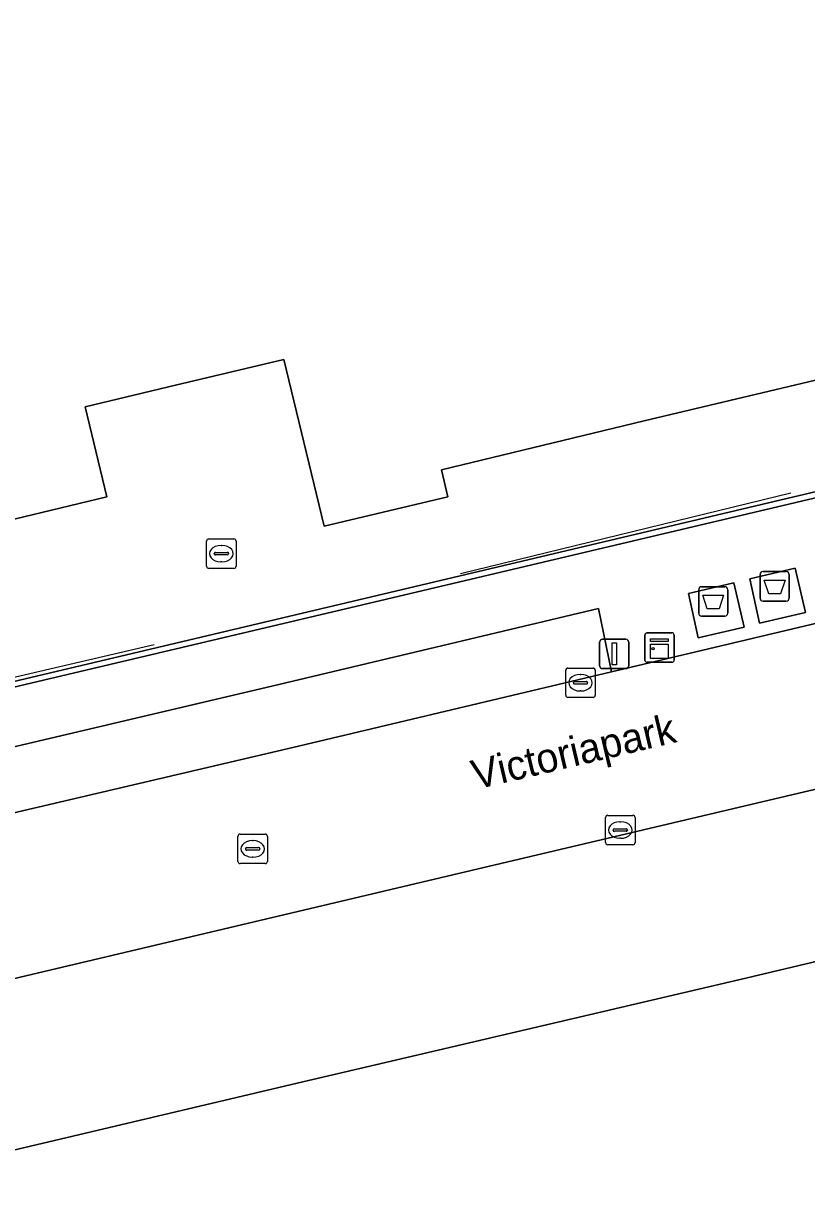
# Model space of a CAD drawing. Extents: x 160675 to 161153, y 383241 to 383714.
# Drawn here: x 160916.35 to 160942.94, y 383443.78 to 383483.75 of the extents above; entities that cross this region are included whole.
import ezdxf

# ---------------------------------------------------------------- set-up
doc = ezdxf.new("R2010")
doc.units = 0
for name, color, linetype in [('IMGEO_Afval_apart_plaats', 7, 'Continuous'), ('IMGEO_Groenvoorziening', 7, 'Continuous'), ('IMGEO_Kast', 7, 'Continuous'), ('IMGEO_Kolk', 7, 'Continuous'), ('IMGEO_Lichtmast', 7, 'Continuous'), ('IMGEO_Lijnafwatering', 7, 'Continuous'), ('IMGEO_Muur', 7, 'Continuous'), ('IMGEO_Openbare_ruimte_label', 7, 'Continuous'), ('IMGEO_Pand', 7, 'Continuous'), ('IMGEO_Parkeervlak_gesloten', 7, 'Continuous'), ('IMGEO_Parkeervlak_open', 7, 'Continuous'), ('IMGEO_Rijbaan_lokaal_gesloten', 7, 'Continuous'), ('IMGEO_Rioolput', 7, 'Continuous'), ('IMGEO_Voetpad_gesloten', 7, 'Continuous'), ('IMGEO_Voetpad_open', 7, 'Continuous')]:
    doc.layers.add(name, color=color, linetype=linetype)

msp = doc.modelspace()

# ---------------------------------------------------------------- linework, layer by layer
at = {"layer": 'IMGEO_Afval_apart_plaats'}
for p, q in [((160941.467, 383465.139), (160942.257, 383465.139)), ((160942.257, 383465.139), (160941.467, 383465.139)), ((160941.367, 383464.239), (160941.367, 383465.039)), ((160941.367, 383465.039), (160941.367, 383464.239)), ((160942.357, 383465.039), (160942.357, 383464.239)), ((160942.357, 383464.239), (160942.357, 383465.039)), ((160939.282, 383463.725), (160939.282, 383464.525)), ((160939.282, 383464.525), (160939.282, 383463.725)), ((160939.382, 383464.625), (160940.172, 383464.625)), ((160940.172, 383464.625), (160939.382, 383464.625)), ((160940.272, 383464.525), (160940.272, 383463.725)), ((160940.272, 383463.725), (160940.272, 383464.525)), ((160942.257, 383464.139), (160941.467, 383464.139)), ((160941.467, 383464.139), (160942.257, 383464.139)), ((160940.172, 383463.625), (160939.382, 383463.625)), ((160939.382, 383463.625), (160940.172, 383463.625))]:
    msp.add_line(p, q, dxfattribs=at)
for points in [[(160941.51, 383464.853), (160942.214, 383464.853), (160942.065, 383464.383), (160941.659, 383464.383), (160941.51, 383464.853)], [(160939.425, 383464.339), (160940.129, 383464.339), (160939.98, 383463.869), (160939.574, 383463.869), (160939.425, 383464.339)]]:
    msp.add_lwpolyline(points, dxfattribs=at)
for centre, start, end in [((160941.467, 383465.039), 90, 180), ((160941.467, 383465.039), 90, 180), ((160942.257, 383465.039), 0, 90), ((160942.257, 383465.039), 360, 90), ((160939.382, 383464.525), 90, 180), ((160939.382, 383464.525), 90, 180), ((160940.172, 383464.525), 0, 90), ((160940.172, 383464.525), 360, 90), ((160941.467, 383464.239), 180, 270), ((160941.467, 383464.239), 180, 270), ((160942.257, 383464.239), 270, 0), ((160942.257, 383464.239), 270, 0), ((160939.382, 383463.725), 180, 270), ((160939.382, 383463.725), 180, 270), ((160940.172, 383463.725), 270, 0), ((160940.172, 383463.725), 270, 0)]:
    msp.add_arc(centre, 0.1, start, end, dxfattribs=at)
at = {"layer": 'IMGEO_Groenvoorziening'}
msp.add_lwpolyline([(160961.401, 383438.272), (160959.945, 383443.924), (160957.181, 383455.143), (160948.323, 383453.092), (160940.889, 383451.334), (160925.647, 383447.762), (160912.456, 383444.655), (160912.313, 383445.09), (160912.097, 383445.102), (160911.285, 383444.92), (160908.049, 383444.567), (160904.275, 383444.678), (160902.028, 383444.954), (160902.501, 383446.376), (160901.449, 383446.503), (160900.213, 383446.777), (160898.49, 383441.561)], dxfattribs=at)
at = {"layer": 'IMGEO_Kast'}
for p, q in [((160937.45, 383462.135), (160937.45, 383462.976)), ((160937.45, 383462.976), (160937.45, 383462.135)), ((160937.525, 383463.06), (160938.366, 383463.06)), ((160938.366, 383463.06), (160937.525, 383463.06)), ((160938.45, 383462.985), (160938.45, 383462.144)), ((160938.45, 383462.144), (160938.45, 383462.985)), ((160938.375, 383462.06), (160937.534, 383462.06)), ((160937.534, 383462.06), (160938.375, 383462.06))]:
    msp.add_line(p, q, dxfattribs=at)
for points in [[(160937.645, 383462.85), (160938.245, 383462.85), (160938.245, 383462.765), (160937.645, 383462.765), (160937.645, 383462.85)], [(160937.645, 383462.675), (160938.245, 383462.675), (160938.245, 383462.186), (160937.645, 383462.186), (160937.645, 383462.675)]]:
    msp.add_lwpolyline(points, dxfattribs=at)
msp.add_circle((160937.729, 383462.524), 0.0377, dxfattribs=at)
for centre, start, end in [((160938.372, 383462.982), 2.4484, 94.2845), ((160938.372, 383462.982), 2.4484, 94.2845), ((160937.528, 383462.982), 92.4484, 184.2845), ((160937.528, 383462.982), 92.4484, 184.2845), ((160937.528, 383462.138), 182.4484, 274.2845), ((160937.528, 383462.138), 182.4484, 274.2845), ((160938.372, 383462.138), 272.4484, 4.2845), ((160938.372, 383462.138), 272.4484, 4.2845)]:
    msp.add_arc(centre, 0.0779, start, end, dxfattribs=at)
at = {"layer": 'IMGEO_Kolk'}
for p, q in [((160922.567, 383465.323), (160922.567, 383466.175)), ((160922.642, 383466.249), (160923.494, 383466.249)), ((160923.055, 383466.029), (160923.08, 383466.029)), ((160923.568, 383466.175), (160923.568, 383465.323)), ((160922.826, 383465.743), (160922.826, 383465.755)), ((160923.264, 383465.706), (160922.866, 383465.706)), ((160922.869, 383465.792), (160923.267, 383465.792)), ((160923.078, 383465.469), (160923.053, 383465.469)), ((160923.31, 383465.755), (160923.31, 383465.743)), ((160923.494, 383465.249), (160922.642, 383465.249)), ((160934.841, 383461.864), (160935.693, 383461.864)), ((160934.766, 383460.938), (160934.766, 383461.79)), ((160935.254, 383461.644), (160935.279, 383461.644)), ((160935.767, 383461.79), (160935.767, 383460.938)), ((160935.025, 383461.358), (160935.025, 383461.37)), ((160935.463, 383461.321), (160935.065, 383461.321)), ((160935.068, 383461.407), (160935.466, 383461.407)), ((160935.277, 383461.084), (160935.252, 383461.084)), ((160935.509, 383461.37), (160935.509, 383461.358)), ((160935.693, 383460.864), (160934.841, 383460.864)), ((160936.119, 383455.934), (160936.119, 383456.786)), ((160936.194, 383456.86), (160937.046, 383456.86)), ((160937.12, 383456.786), (160937.12, 383455.934)), ((160936.378, 383456.354), (160936.378, 383456.366)), ((160936.816, 383456.317), (160936.418, 383456.317)), ((160936.421, 383456.403), (160936.819, 383456.403)), ((160936.607, 383456.64), (160936.632, 383456.64)), ((160936.862, 383456.366), (160936.862, 383456.354)), ((160936.63, 383456.08), (160936.605, 383456.08)), ((160937.046, 383455.86), (160936.194, 383455.86))]:
    msp.add_line(p, q, dxfattribs=at)
for points in [[(160922.567, 383465.323), (160922.567, 383466.175)], [(160922.642, 383466.249), (160923.494, 383466.249)], [(160923.568, 383466.175), (160923.568, 383465.323)], [(160923.494, 383465.249), (160922.642, 383465.249)], [(160934.841, 383461.864), (160935.693, 383461.864)], [(160934.766, 383460.938), (160934.766, 383461.79)], [(160935.767, 383461.79), (160935.767, 383460.938)], [(160935.693, 383460.864), (160934.841, 383460.864)], [(160936.119, 383455.934), (160936.119, 383456.786)], [(160936.194, 383456.86), (160937.046, 383456.86)], [(160937.12, 383456.786), (160937.12, 383455.934)], [(160937.046, 383455.86), (160936.194, 383455.86)]]:
    msp.add_lwpolyline(points, dxfattribs=at)
for centre, radius, start, end in [((160922.644, 383466.173), 0.0765, 91.552, 178.448), ((160922.644, 383466.173), 0.0765, 91.552, 178.448), ((160923.492, 383466.173), 0.0765, 1.552, 88.448), ((160923.492, 383466.173), 0.0765, 1.552, 88.448), ((160922.866, 383465.752), 0.0403, 85.8775, 175.7526), ((160922.863, 383465.742), 0.0366, 178.938, 274.7102), ((160923.267, 383465.749), 0.043, 264.8664, 352.4533), ((160923.271, 383465.754), 0.0386, 1.7309, 96.639), ((160922.644, 383465.325), 0.0765, 181.552, 268.448), ((160922.644, 383465.325), 0.0765, 181.552, 268.448), ((160923.492, 383465.325), 0.0765, 271.552, 358.448), ((160923.492, 383465.325), 0.0765, 271.552, 358.448), ((160934.843, 383461.788), 0.0765, 91.552, 178.448), ((160934.843, 383461.788), 0.0765, 91.552, 178.448), ((160935.691, 383461.788), 0.0765, 1.552, 88.448), ((160935.691, 383461.788), 0.0765, 1.552, 88.448), ((160935.065, 383461.367), 0.0403, 85.8775, 175.7526), ((160935.062, 383461.357), 0.0366, 178.938, 274.7102), ((160935.466, 383461.364), 0.043, 264.8664, 352.4533), ((160935.47, 383461.369), 0.0386, 1.7309, 96.639), ((160934.843, 383460.94), 0.0765, 181.552, 268.448), ((160934.843, 383460.94), 0.0765, 181.552, 268.448), ((160935.691, 383460.94), 0.0765, 271.552, 358.448), ((160935.691, 383460.94), 0.0765, 271.552, 358.448), ((160936.196, 383456.784), 0.0765, 91.552, 178.448), ((160936.196, 383456.784), 0.0765, 91.552, 178.448), ((160937.044, 383456.784), 0.0765, 1.552, 88.448), ((160937.044, 383456.784), 0.0765, 1.552, 88.448), ((160936.418, 383456.363), 0.0403, 85.8775, 175.7526), ((160936.415, 383456.353), 0.0366, 178.938, 274.7102), ((160936.819, 383456.36), 0.043, 264.8664, 352.4533), ((160936.823, 383456.365), 0.0386, 1.7309, 96.639), ((160936.196, 383455.936), 0.0765, 181.552, 268.448), ((160936.196, 383455.936), 0.0765, 181.552, 268.448), ((160937.044, 383455.936), 0.0765, 271.552, 358.448), ((160937.044, 383455.936), 0.0765, 271.552, 358.448)]:
    msp.add_arc(centre, radius, start, end, dxfattribs=at)
for centre, major_axis, ratio, start_param, end_param in [((160923.054, 383465.749), (-0.387, 0.002), 0.722429, 4.712389, 7.853982), ((160923.079, 383465.749), (-0.39, 0.002), 0.717154, 1.570796, 4.712389), ((160935.253, 383461.364), (-0.387, 0.002), 0.722429, 4.712389, 7.853982), ((160935.278, 383461.364), (-0.39, 0.002), 0.717154, 1.570796, 4.712389), ((160936.606, 383456.36), (-0.387, 0.002), 0.722429, 4.712389, 7.853982), ((160936.631, 383456.36), (-0.39, 0.002), 0.717154, 1.570796, 4.712389)]:
    msp.add_ellipse(centre, major_axis=major_axis, ratio=ratio, start_param=start_param, end_param=end_param, dxfattribs=at)
at = {"layer": 'IMGEO_Lichtmast'}
for p, q in [((160935.918, 383461.942), (160935.918, 383462.742)), ((160935.918, 383462.742), (160935.918, 383461.942)), ((160936.018, 383462.842), (160936.808, 383462.842)), ((160936.808, 383462.842), (160936.018, 383462.842)), ((160936.908, 383462.742), (160936.908, 383461.942)), ((160936.908, 383461.942), (160936.908, 383462.742)), ((160936.808, 383461.842), (160936.018, 383461.842)), ((160936.018, 383461.842), (160936.808, 383461.842))]:
    msp.add_line(p, q, dxfattribs=at)
msp.add_lwpolyline([(160936.338, 383462.717), (160936.488, 383462.717), (160936.488, 383461.967), (160936.338, 383461.967), (160936.338, 383462.717)], dxfattribs=at)
for centre, start, end in [((160936.018, 383462.742), 90, 180), ((160936.018, 383462.742), 90, 180), ((160936.808, 383462.742), 0, 90), ((160936.808, 383462.742), 360, 90), ((160936.018, 383461.942), 180, 270), ((160936.018, 383461.942), 180, 270), ((160936.808, 383461.942), 270, 0), ((160936.808, 383461.942), 270, 0)]:
    msp.add_arc(centre, 0.1, start, end, dxfattribs=at)
at = {"layer": 'IMGEO_Lijnafwatering'}
for points in [[(160931.192, 383465.07), (160942.413, 383467.815)], [(160911.987, 383460.608), (160920.79, 383462.662)]]:
    msp.add_lwpolyline(points, dxfattribs=at)
at = {"layer": 'IMGEO_Muur'}
msp.add_lwpolyline([(160962.002, 383472.066), (160961.939, 383472.274), (160912.322, 383460.539), (160909.084, 383459.778), (160908.505, 383459.64), (160907.11, 383459.309), (160907.173, 383459.127), (160909.143, 383459.613), (160912.316, 383460.345)], close=True, dxfattribs=at)
at = {"layer": 'IMGEO_Pand'}
msp.add_lwpolyline([(160915.401, 383466.768), (160919.181, 383467.683), (160918.441, 383470.74), (160921.51, 383471.475), (160925.187, 383472.344), (160926.562, 383466.682), (160930.76, 383467.683), (160930.542, 383468.594), (160937.433, 383470.262), (160961.1, 383475.879), (160994.002, 383483.688)], dxfattribs=at)
at = {"layer": 'IMGEO_Parkeervlak_gesloten'}
msp.add_lwpolyline([(160995.466, 383470.147), (160980.701, 383466.632), (160966.645, 383463.289), (160949.112, 383459.134), (160931.555, 383454.985), (160911.346, 383450.209), (160912.313, 383445.09), (160912.456, 383444.655), (160925.647, 383447.762), (160940.889, 383451.334), (160948.323, 383453.092), (160957.181, 383455.143), (160959.945, 383443.924), (160961.401, 383438.272), (160969.602, 383440.105), (160985.135, 383443.735), (161000.128, 383447.369)], dxfattribs=at)
at = {"layer": 'IMGEO_Parkeervlak_open'}
msp.add_lwpolyline([(160935.883, 383463.884), (160925.023, 383461.307), (160908.315, 383457.371), (160908.819, 383455.316), (160909.438, 383455.409), (160925.692, 383459.21), (160936.322, 383461.732)], close=True, dxfattribs=at)
at = {"layer": 'IMGEO_Rijbaan_lokaal_gesloten'}
for points in [[(160998.276, 383476.453), (160994.586, 383475.579), (160976.658, 383471.303), (160965.222, 383468.589), (160936.322, 383461.732), (160925.692, 383459.21), (160909.438, 383455.409), (160908.819, 383455.316)], [(160911.167, 383450.167), (160911.346, 383450.209), (160931.555, 383454.985), (160949.112, 383459.134), (160966.645, 383463.289), (160980.701, 383466.632), (160995.466, 383470.147)]]:
    msp.add_lwpolyline(points, dxfattribs=at)
at = {"layer": 'IMGEO_Rioolput'}
for p, q in [((160923.631, 383455.295), (160923.631, 383456.147)), ((160923.706, 383456.221), (160924.558, 383456.221)), ((160924.119, 383456.001), (160924.144, 383456.001)), ((160924.632, 383456.147), (160924.632, 383455.295)), ((160923.89, 383455.715), (160923.89, 383455.727)), ((160924.328, 383455.678), (160923.93, 383455.678)), ((160923.933, 383455.764), (160924.331, 383455.764)), ((160924.374, 383455.727), (160924.374, 383455.715)), ((160924.558, 383455.221), (160923.706, 383455.221)), ((160924.142, 383455.441), (160924.117, 383455.441))]:
    msp.add_line(p, q, dxfattribs=at)
for points in [[(160923.631, 383455.295), (160923.631, 383456.147)], [(160923.706, 383456.221), (160924.558, 383456.221)], [(160924.632, 383456.147), (160924.632, 383455.295)], [(160924.558, 383455.221), (160923.706, 383455.221)]]:
    msp.add_lwpolyline(points, dxfattribs=at)
for centre, radius, start, end in [((160923.708, 383456.145), 0.0765, 91.552, 178.448), ((160923.708, 383456.145), 0.0765, 91.552, 178.448), ((160924.556, 383456.145), 0.0765, 1.552, 88.448), ((160924.556, 383456.145), 0.0765, 1.552, 88.448), ((160923.93, 383455.724), 0.0403, 85.8775, 175.7526), ((160923.927, 383455.714), 0.0366, 178.938, 274.7102), ((160924.331, 383455.721), 0.043, 264.8664, 352.4533), ((160924.335, 383455.726), 0.0386, 1.7309, 96.639), ((160923.708, 383455.297), 0.0765, 181.552, 268.448), ((160923.708, 383455.297), 0.0765, 181.552, 268.448), ((160924.556, 383455.297), 0.0765, 271.552, 358.448), ((160924.556, 383455.297), 0.0765, 271.552, 358.448)]:
    msp.add_arc(centre, radius, start, end, dxfattribs=at)
for centre, major_axis, ratio, start_param, end_param in [((160924.118, 383455.721), (-0.387, 0.002), 0.722429, 4.712389, 7.853982), ((160924.143, 383455.721), (-0.39, 0.002), 0.717154, 1.570796, 4.712389)]:
    msp.add_ellipse(centre, major_axis=major_axis, ratio=ratio, start_param=start_param, end_param=end_param, dxfattribs=at)
at = {"layer": 'IMGEO_Voetpad_gesloten'}
for points in [[(160942.562, 383465.255), (160941.019, 383464.896), (160941.35, 383463.386), (160942.908, 383463.752)], [(160940.477, 383464.755), (160938.934, 383464.395), (160939.265, 383462.885), (160940.823, 383463.251)]]:
    msp.add_lwpolyline(points, close=True, dxfattribs=at)
at = {"layer": 'IMGEO_Voetpad_open'}
for points in [[(161004.491, 383485.269), (160999.63, 383484.142), (160998.46, 383483.872), (160998.483, 383483.774), (160994.296, 383482.789), (160994.002, 383483.688), (160961.1, 383475.879), (160961.939, 383472.274), (160962.002, 383472.066), (160912.316, 383460.345), (160909.143, 383459.613), (160907.173, 383459.127), (160907.11, 383459.309), (160906.15, 383463.208), (160875.621, 383455.906), (160852.917, 383450.548), (160850.704, 383450.032), (160848.255, 383449.977), (160845.447, 383450.327)], [(160908.819, 383455.316), (160908.315, 383457.371), (160925.023, 383461.307), (160935.883, 383463.884), (160936.322, 383461.732), (160965.222, 383468.589), (160964.683, 383470.898), (160980.237, 383474.595), (160994.071, 383477.858), (160994.586, 383475.579), (160998.276, 383476.453)], [(160912.322, 383460.539), (160961.939, 383472.274), (160961.1, 383475.879), (160937.433, 383470.262), (160930.542, 383468.594), (160930.76, 383467.683), (160926.562, 383466.682), (160925.187, 383472.344), (160921.51, 383471.475), (160918.441, 383470.74), (160919.181, 383467.683), (160915.401, 383466.768)]]:
    msp.add_lwpolyline(points, dxfattribs=at)
for points in [[(160942.562, 383465.255), (160942.908, 383463.752), (160941.35, 383463.386), (160941.019, 383464.896)], [(160940.477, 383464.755), (160940.823, 383463.251), (160939.265, 383462.885), (160938.934, 383464.395)]]:
    msp.add_lwpolyline(points, close=True, dxfattribs=at)

# ---------------------------------------------------------------- texts
at = {"layer": 'IMGEO_Openbare_ruimte_label'}
msp.add_text('Victoriapark', height=1, rotation=13.2996, dxfattribs=at).set_placement((160931.705, 383457.729))

doc.saveas('drawing.dxf')
